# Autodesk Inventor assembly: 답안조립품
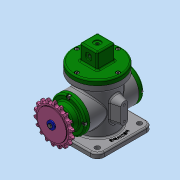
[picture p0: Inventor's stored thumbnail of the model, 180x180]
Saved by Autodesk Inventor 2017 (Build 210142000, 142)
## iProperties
Part Number: 답안조립품
Material: 일반
Document SubType Name: Assembly
Designer: user
Author: user
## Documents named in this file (19)
- C:\Users\user\Desktop\710306V1007\답안조립품.iam
- C:\Users\user\Desktop\710306V1007\본체.ipt
- C:\Users\user\Desktop\710306V1007\E-링.ipt
- C:\Users\user\Desktop\710306V1007\덮개.ipt
- C:\Users\user\Desktop\710306V1007\뒤커버.ipt
- C:\Users\user\Desktop\710306V1007\링크.ipt
- C:\Users\user\Desktop\710306V1007\멈춤나사 M3.ipt
- C:\Users\user\Desktop\710306V1007\베어링 17 x 40 x 12.ipt
- C:\Users\user\Desktop\710306V1007\볼트 M4 x 8.ipt
- C:\Users\user\Desktop\710306V1007\볼트 M4 x 10.ipt
- C:\Users\user\Desktop\710306V1007\스프로킷.ipt
- C:\Users\user\Desktop\710306V1007\슬라이더.ipt
- C:\Users\user\Desktop\710306V1007\앞커버.ipt
- C:\Users\user\Desktop\710306V1007\오일 실 17 30 8.ipt
- C:\Users\user\Desktop\710306V1007\와셔 4x16.ipt
- C:\Users\user\Desktop\710306V1007\클레비스 핀 6 x 22.ipt
- 클레비스 핀 6 x 22.ipt
- C:\Users\user\Desktop\710306V1007\키 4 x 4 x 12.ipt
- C:\Users\user\Desktop\710306V1007\편심축.ipt
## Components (1 placed, 1 different names)
1. E-링:1
